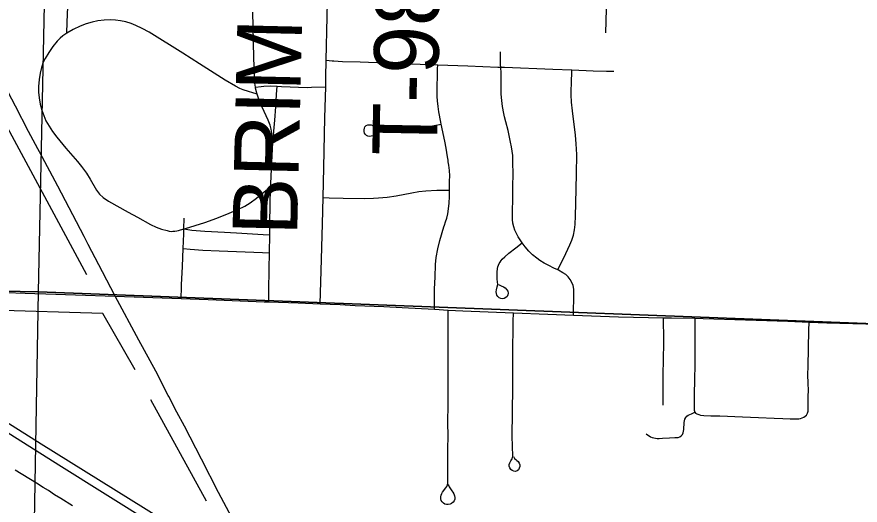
# Model space of a CAD drawing. Extents: x -59 to 43, y 0 to 22.
# Drawn here: x 24.177 to 24.918, y 18.165 to 18.594 of the extents above; entities that cross this region are included whole.
import ezdxf

# ---------------------------------------------------------------- set-up
doc = ezdxf.new("R2010")
doc.units = 0
for name, color, linetype in [('Default', 7, 'Continuous'), ('GM_X_City_Street', 7, 'Continuous'), ('GM_X_County_Road', 7, 'Continuous'), ('GM_X_Minor_River', 7, 'Continuous'), ('GM_X_Rail_Line', 7, 'Continuous'), ('GM_X_Section', 7, 'Continuous'), ('GM_X_State_Route', 7, 'Continuous'), ('GM_X_Township_Road', 7, 'Continuous'), ('GM_X_Township_Road_Text', 7, 'Continuous')]:
    doc.layers.add(name, color=color, linetype=linetype)

msp = doc.modelspace()

# ---------------------------------------------------------------- linework, layer by layer
at = {"layer": 'Default'}
for points in [[(23.51667, 19.36712), (23.51667, 18.36457), (24.19635, 18.35229), (24.21701, 19.34715)], [(23.51667, 18.36457), (23.51667, 17.35203), (23.63449, 17.34676), (24.1786, 17.34343), (24.19635, 18.35229)]]:
    msp.add_lwpolyline(points, close=True, dxfattribs=at)
at = {"layer": 'GM_X_City_Street'}
for points in [[(24.66612, 18.33172), (24.66623, 18.33912), (24.6663, 18.34325), (24.66629, 18.34753), (24.66646, 18.35082), (24.66645, 18.35444), (24.66588, 18.35775), (24.66475, 18.36048), (24.66327, 18.36301), (24.66144, 18.36531), (24.6593, 18.36733), (24.65691, 18.36904), (24.65293, 18.37112), (24.65228, 18.37143), (24.64874, 18.37311), (24.64457, 18.37521), (24.64045, 18.37742), (24.63644, 18.37987), (24.63387, 18.38169), (24.63021, 18.38469), (24.62683, 18.38802), (24.62374, 18.3916), (24.621, 18.39528), (24.61751, 18.40066), (24.61598, 18.40342), (24.61466, 18.40631), (24.61363, 18.40934), (24.61299, 18.41245), (24.61265, 18.41559), (24.61255, 18.42031), (24.61268, 18.42574), (24.61279, 18.43107), (24.61295, 18.43699), (24.61296, 18.44506), (24.61311, 18.45559), (24.61294, 18.46611), (24.61277, 18.47203), (24.61161, 18.47943), (24.61079, 18.48355), (24.60983, 18.48795), (24.60862, 18.49392), (24.60666, 18.50135), (24.60551, 18.50587), (24.6049, 18.50895), (24.6039, 18.51509), (24.60293, 18.52281), (24.60259, 18.52596), (24.60254, 18.53207), (24.60268, 18.54243), (24.6027, 18.54415), (24.60227, 18.54948), (24.60203, 18.55152), (24.602, 18.55344), (24.60203, 18.5601), (24.60203, 18.56296)], [(24.44906, 18.55561), (24.45417, 18.5551), (24.4557, 18.55494), (24.46342, 18.55453), (24.4789, 18.55412), (24.50827, 18.55302), (24.54686, 18.55163), (24.57338, 18.55053), (24.59975, 18.54959), (24.60227, 18.54948), (24.60568, 18.54937), (24.64785, 18.54778), (24.66459, 18.54713), (24.68353, 18.54637), (24.69525, 18.54606), (24.70154, 18.546)], [(24.54401, 18.33695), (24.54395, 18.34982), (24.5442, 18.35476), (24.54457, 18.36524), (24.54505, 18.37634), (24.54567, 18.38239), (24.5469, 18.38989), (24.54876, 18.39744), (24.5524, 18.40933), (24.55288, 18.41078), (24.55381, 18.41355), (24.55491, 18.41694), (24.55577, 18.42076), (24.55636, 18.42518), (24.557, 18.43014), (24.55724, 18.43582), (24.55729, 18.44149), (24.55737, 18.44942), (24.55743, 18.45408), (24.55716, 18.45874), (24.55652, 18.46335), (24.55618, 18.46635), (24.55603, 18.46782), (24.55559, 18.4708), (24.55426, 18.47837), (24.55306, 18.48444), (24.54996, 18.49952), (24.54961, 18.50119), (24.54784, 18.51033), (24.5472, 18.51491), (24.54676, 18.52001), (24.54651, 18.52371), (24.54645, 18.52725), (24.54646, 18.53024), (24.5465, 18.53178), (24.54657, 18.54267), (24.54675, 18.54814), (24.54686, 18.55163)], [(24.65228, 18.37143), (24.65483, 18.37662), (24.65756, 18.38218), (24.66299, 18.39336), (24.66472, 18.39766), (24.66609, 18.40208), (24.66703, 18.40663), (24.66757, 18.41125), (24.668, 18.41899), (24.66829, 18.42965), (24.66884, 18.45593), (24.66903, 18.4729), (24.66861, 18.48219), (24.66789, 18.48992), (24.66528, 18.51119), (24.66442, 18.51884), (24.66417, 18.52526), (24.66451, 18.53933), (24.66454, 18.54243), (24.66459, 18.54713)], [(24.49589, 18.49355), (24.49471, 18.49304), (24.4935, 18.49204), (24.49222, 18.4909), (24.49112, 18.48984), (24.49009, 18.48921), (24.48855, 18.48884), (24.48694, 18.48874), (24.48551, 18.48888), (24.48426, 18.48936), (24.48339, 18.49028), (24.48253, 18.49163), (24.4822, 18.49306), (24.4822, 18.49442), (24.48249, 18.49593), (24.483, 18.49714), (24.48392, 18.49813), (24.48538, 18.49886), (24.48693, 18.49895), (24.48843, 18.49879), (24.48983, 18.49828), (24.49141, 18.49714), (24.49303, 18.49549), (24.4948, 18.49424), (24.49621, 18.49373), (24.50079, 18.49341), (24.51016, 18.49339), (24.51481, 18.49358), (24.52099, 18.49416), (24.52867, 18.49536), (24.54391, 18.49834), (24.54996, 18.49952)], [(24.44624, 18.43494), (24.45155, 18.43483), (24.464, 18.43458), (24.48269, 18.43432), (24.49044, 18.43443), (24.49499, 18.4347), (24.50264, 18.4354), (24.51031, 18.4365), (24.52406, 18.4392), (24.53018, 18.44026), (24.53634, 18.44095), (24.54626, 18.44149), (24.55317, 18.44149), (24.55729, 18.44149)], [(24.60016, 18.35862), (24.60269, 18.35752), (24.60453, 18.35671), (24.60623, 18.35561), (24.60766, 18.35409), (24.60835, 18.35269), (24.60864, 18.35116), (24.60848, 18.34962), (24.60783, 18.34822), (24.60676, 18.3471), (24.60537, 18.34641), (24.60382, 18.34618), (24.60229, 18.34641), (24.60089, 18.34708), (24.59973, 18.34812), (24.59888, 18.34943), (24.59839, 18.3509), (24.59835, 18.35236), (24.59851, 18.35409), (24.59909, 18.35649), (24.59968, 18.35866), (24.5992, 18.36326), (24.59913, 18.36955), (24.59942, 18.37266), (24.59975, 18.37416), (24.60024, 18.37557), (24.60088, 18.37696), (24.60164, 18.37832), (24.60252, 18.37959), (24.60352, 18.3808), (24.60571, 18.38302), (24.60925, 18.38607), (24.61539, 18.39088), (24.621, 18.39528)], [(24.55621, 18.18341), (24.5564, 18.18248), (24.55695, 18.18108), (24.55815, 18.17913), (24.5592, 18.17754), (24.56006, 18.17637), (24.56111, 18.17482), (24.56171, 18.17315), (24.56197, 18.17162), (24.56183, 18.17008), (24.56127, 18.16866), (24.56034, 18.16744), (24.55913, 18.16647), (24.55772, 18.16581), (24.55621, 18.16547), (24.55466, 18.1655), (24.55317, 18.1659), (24.55185, 18.16668), (24.55077, 18.16778), (24.54999, 18.16912), (24.54955, 18.1706), (24.54949, 18.17214), (24.54978, 18.17365), (24.55037, 18.17508), (24.55117, 18.17641), (24.55405, 18.18007), (24.5549, 18.18137), (24.55551, 18.18277), (24.55582, 18.18428), (24.55576, 18.20442), (24.55589, 18.21059), (24.55583, 18.21525), (24.55597, 18.22454), (24.55589, 18.23848), (24.5561, 18.25241), (24.55593, 18.26325), (24.55613, 18.27409), (24.55605, 18.29113), (24.55616, 18.3283), (24.55615, 18.33622)], [(24.61332, 18.20749), (24.61433, 18.20588), (24.61539, 18.20486), (24.6165, 18.20406), (24.61751, 18.2031), (24.61839, 18.20176), (24.61888, 18.2003), (24.61892, 18.19876), (24.61854, 18.19727), (24.61777, 18.19597), (24.61662, 18.19503), (24.61519, 18.1946), (24.61367, 18.19473), (24.61226, 18.19535), (24.61108, 18.19635), (24.6102, 18.19763), (24.60971, 18.19909), (24.60963, 18.20063), (24.61009, 18.20219), (24.6111, 18.20386), (24.61221, 18.20562), (24.61281, 18.20784), (24.61276, 18.21041), (24.61255, 18.21409), (24.61256, 18.21717), (24.61237, 18.22489), (24.61237, 18.22799), (24.61247, 18.24355), (24.61288, 18.27156), (24.61298, 18.29646), (24.61327, 18.32603), (24.61335, 18.33372)], [(24.74491, 18.2526), (24.74488, 18.25636), (24.74492, 18.26259), (24.74503, 18.26728), (24.74503, 18.27665), (24.74526, 18.29541), (24.74538, 18.30466), (24.74537, 18.30937), (24.74538, 18.31249), (24.74538, 18.31719), (24.7453, 18.32188), (24.74515, 18.32952)], [(24.77277, 18.32898), (24.77278, 18.3166), (24.77264, 18.29927), (24.77256, 18.28701), (24.77247, 18.2763), (24.77222, 18.26079), (24.77198, 18.25305), (24.77202, 18.25021), (24.77215, 18.24841), (24.77267, 18.2465), (24.77326, 18.24574), (24.77459, 18.24496), (24.77608, 18.24441), (24.77758, 18.244), (24.78065, 18.24354), (24.78685, 18.24333), (24.79455, 18.24322), (24.81465, 18.24239), (24.8285, 18.24182), (24.84237, 18.24142), (24.85009, 18.24107), (24.85628, 18.24072), (24.86092, 18.24067), (24.864, 18.24082), (24.86553, 18.24105), (24.86701, 18.24146), (24.8684, 18.24212), (24.86961, 18.24307), (24.87071, 18.24396), (24.87171, 18.24556), (24.87221, 18.24754), (24.87233, 18.25038), (24.87218, 18.25483), (24.87232, 18.26062), (24.87245, 18.26568), (24.87232, 18.27196), (24.87207, 18.27925), (24.87219, 18.2869), (24.87292, 18.31836), (24.87309, 18.32566)], [(24.73004, 18.22751), (24.7312, 18.22651), (24.73246, 18.22565), (24.73381, 18.22494), (24.73523, 18.22436), (24.7367, 18.22392), (24.7382, 18.22362), (24.73972, 18.22347), (24.74125, 18.22345), (24.74432, 18.22363), (24.75046, 18.22391), (24.75507, 18.22417), (24.75813, 18.2244), (24.75956, 18.22495), (24.76079, 18.22582), (24.76176, 18.22697), (24.76245, 18.22833), (24.76286, 18.22979), (24.76307, 18.23132), (24.7633, 18.2375), (24.76354, 18.23902), (24.76397, 18.24048), (24.76468, 18.24181), (24.76568, 18.24294), (24.76694, 18.24381), (24.76833, 18.24448), (24.7697, 18.24512), (24.77267, 18.2465)], [(24.22605, 18.16437), (24.21591, 18.17074), (24.21045, 18.17411), (24.20514, 18.17763), (24.20034, 18.18051), (24.1945, 18.18423), (24.17593, 18.19577)]]:
    msp.add_lwpolyline(points, dxfattribs=at)
at = {"layer": 'GM_X_County_Road'}
for p, q in [((24.26357, 18.34829), (24.32145, 18.34626)), ((24.54401, 18.33695), (24.55615, 18.33622))]:
    msp.add_line(p, q, dxfattribs=at)
for points in [[(24.05155, 18.35317), (24.05354, 18.35315), (24.10325, 18.35249), (24.12329, 18.35228), (24.15918, 18.3519), (24.19308, 18.35084), (24.20267, 18.35054), (24.22887, 18.34957), (24.26357, 18.34829)], [(24.32145, 18.34626), (24.34518, 18.34542), (24.39446, 18.34351), (24.39853, 18.34336), (24.42427, 18.34244), (24.44365, 18.34165)], [(24.44365, 18.34165), (24.46127, 18.34096), (24.47442, 18.34035), (24.49944, 18.3392), (24.51574, 18.33845), (24.54401, 18.33695)], [(24.55615, 18.33622), (24.56906, 18.33547), (24.61335, 18.33372)], [(24.61335, 18.33372), (24.64352, 18.33253), (24.66612, 18.33172)], [(24.66612, 18.33172), (24.70553, 18.33029), (24.74515, 18.32952)], [(24.74515, 18.32952), (24.75211, 18.32939), (24.77277, 18.32898)], [(24.77277, 18.32898), (24.77999, 18.32878), (24.85449, 18.32633), (24.87309, 18.32566), (24.88863, 18.3251), (24.92277, 18.32407), (24.94397, 18.32326)]]:
    msp.add_lwpolyline(points, dxfattribs=at)
at = {"layer": 'GM_X_Minor_River'}
for points in [[(24.70035, 18.8265), (24.69746, 18.75395), (24.6965, 18.66351), (24.69414, 18.57955)], [(24.23865, 18.36726), (24.0972, 18.62991), (23.99498, 18.82037)], [(24.28106, 18.2836), (24.2528, 18.33316), (24.15497, 18.33614), (24.06698, 18.33704), (23.98922, 18.33812), (23.91035, 18.33998), (23.88019, 18.34013), (23.75221, 18.34297), (23.66576, 18.34536), (23.55881, 18.34701), (23.51667, 18.34767)], [(24.34375, 18.16839), (24.29499, 18.25749)]]:
    msp.add_lwpolyline(points, dxfattribs=at)
at = {"layer": 'GM_X_Rail_Line'}
for points in [[(24.85953, 17.57035), (24.84019, 17.76617), (24.82935, 17.81016), (24.79303, 17.84892), (24.19874, 18.21842), (23.51667, 18.64966)], [(23.51667, 18.64098), (24.21418, 18.20034), (24.75495, 17.86208), (24.75829, 17.57829), (24.85953, 17.57035)]]:
    msp.add_lwpolyline(points, dxfattribs=at)
at = {"layer": 'GM_X_Section'}
for points in [[(24.21701, 19.34715), (25.1966, 19.31798), (25.19616, 19.28425), (25.1906, 18.3142), (24.19635, 18.35229)], [(24.19635, 18.35229), (25.1906, 18.3142), (25.19112, 18.29638), (25.18772, 17.31279), (24.42943, 17.3409), (24.1786, 17.34343)]]:
    msp.add_lwpolyline(points, close=True, dxfattribs=at)
at = {"layer": 'GM_X_State_Route'}
msp.add_line((24.19713, 18.47511), (24.1957, 18.47781), dxfattribs=at)
for points in [[(24.1957, 18.47781), (24.18757, 18.4931), (24.17599, 18.51527), (24.16956, 18.52759), (24.14808, 18.56904), (24.13274, 18.59839)], [(24.26357, 18.34829), (24.2526, 18.36968), (24.24927, 18.37607), (24.24002, 18.39377), (24.23629, 18.40091), (24.21313, 18.445), (24.19713, 18.47511)], [(24.3102, 18.2612), (24.29921, 18.28243), (24.28436, 18.30977), (24.26357, 18.34829)], [(24.37768, 18.13223), (24.35431, 18.17608), (24.3395, 18.20518), (24.32441, 18.23417), (24.31783, 18.24653), (24.31066, 18.26031), (24.3102, 18.2612)]]:
    msp.add_lwpolyline(points, dxfattribs=at)
at = {"layer": 'GM_X_Township_Road'}
for p, q in [((24.32406, 18.40744), (24.32427, 18.41679)), ((24.39905, 18.38655), (24.39932, 18.40228))]:
    msp.add_line(p, q, dxfattribs=at)
for points in [[(24.44906, 18.55561), (24.44987, 18.59362), (24.4506, 18.63403), (24.4513, 18.67755), (24.4517, 18.69637)], [(24.22113, 18.57934), (24.22152, 18.58889), (24.22209, 18.60254), (24.22225, 18.60563)], [(24.38688, 18.53182), (24.38641, 18.53538), (24.38542, 18.5578), (24.38479, 18.58519), (24.38455, 18.59767)], [(24.38836, 18.52566), (24.38076, 18.52808), (24.37602, 18.52958), (24.37316, 18.53079), (24.36931, 18.5328), (24.3602, 18.53814), (24.33767, 18.5525), (24.32301, 18.56187), (24.29345, 18.58023), (24.28746, 18.58353), (24.28187, 18.58622), (24.27782, 18.58781), (24.27306, 18.58924), (24.2682, 18.59024), (24.26388, 18.59077), (24.25953, 18.59095), (24.25395, 18.59073), (24.24839, 18.59006), (24.24353, 18.58908), (24.23816, 18.58751), (24.23294, 18.58551), (24.22675, 18.58261), (24.22113, 18.57934)], [(24.22113, 18.57934), (24.21778, 18.57703), (24.21542, 18.57503), (24.21283, 18.57235), (24.20889, 18.56755), (24.20533, 18.56246), (24.20209, 18.55716), (24.2005, 18.55379), (24.19885, 18.5491), (24.19764, 18.54428), (24.19675, 18.53876), (24.1963, 18.53257), (24.19637, 18.5276), (24.19682, 18.52265), (24.19778, 18.51714), (24.19921, 18.51173), (24.20086, 18.50705), (24.20288, 18.50251), (24.20552, 18.49758), (24.20855, 18.49287), (24.2123, 18.48792), (24.22039, 18.4785), (24.23058, 18.46676), (24.23403, 18.46237), (24.23841, 18.45635), (24.24171, 18.45108), (24.24731, 18.44138), (24.24993, 18.43793), (24.25312, 18.43501), (24.25778, 18.43192), (24.27508, 18.42211), (24.28334, 18.41779), (24.29471, 18.41139), (24.29977, 18.40901), (24.30442, 18.40727), (24.30921, 18.40596), (24.31111, 18.40557), (24.31288, 18.40534), (24.31437, 18.40535), (24.31596, 18.40547), (24.31787, 18.40571), (24.31925, 18.40598), (24.32406, 18.40744)], [(24.44853, 18.53213), (24.44875, 18.54079), (24.44906, 18.55561)], [(24.38688, 18.53182), (24.39172, 18.53246), (24.3942, 18.53278), (24.39981, 18.53296), (24.40577, 18.53278)], [(24.38836, 18.52566), (24.38803, 18.52666), (24.387, 18.53097), (24.38688, 18.53182)], [(24.40214, 18.4834), (24.40381, 18.50287), (24.40482, 18.51475), (24.40538, 18.52542), (24.40577, 18.53278)], [(24.40577, 18.53278), (24.40981, 18.53265), (24.4323, 18.53177), (24.43604, 18.53185), (24.44853, 18.53213)], [(24.44624, 18.43494), (24.44701, 18.46153), (24.44785, 18.50505), (24.44853, 18.53213)], [(24.40214, 18.4834), (24.40176, 18.48459), (24.40155, 18.48585), (24.40146, 18.48713), (24.40131, 18.49146), (24.40074, 18.49502), (24.39975, 18.4985), (24.39796, 18.50306), (24.39263, 18.51429), (24.3898, 18.52128), (24.38836, 18.52566)], [(24.40032, 18.44475), (24.40047, 18.44747), (24.40093, 18.45987), (24.40214, 18.4834)], [(24.32406, 18.40744), (24.32547, 18.40788), (24.34223, 18.41318), (24.35283, 18.41687), (24.36387, 18.42116), (24.37129, 18.42441), (24.37739, 18.42754), (24.38216, 18.43049), (24.3877, 18.43452), (24.39448, 18.44001), (24.40032, 18.44475)], [(24.39932, 18.40228), (24.39942, 18.40772), (24.39968, 18.43325), (24.40032, 18.44475)], [(24.44365, 18.34165), (24.44453, 18.37071), (24.44568, 18.4118), (24.44624, 18.43494)], [(24.32339, 18.39029), (24.32396, 18.40309), (24.32406, 18.40744)], [(24.32406, 18.40744), (24.33092, 18.40649), (24.34223, 18.4056), (24.3596, 18.40474), (24.37015, 18.40413), (24.39374, 18.40264), (24.39932, 18.40228)], [(24.32145, 18.34626), (24.32188, 18.35643), (24.32196, 18.35829), (24.3227, 18.37447), (24.32339, 18.39029)], [(24.32339, 18.39029), (24.32951, 18.3898), (24.34069, 18.38888), (24.35501, 18.38814), (24.39304, 18.38677), (24.39905, 18.38655)], [(24.39853, 18.34336), (24.39862, 18.35297), (24.3988, 18.37227), (24.39905, 18.38655)]]:
    msp.add_lwpolyline(points, dxfattribs=at)

# ---------------------------------------------------------------- texts
at = {"layer": 'GM_X_Township_Road_Text'}
for s, rotation, p in [('T-98', 88.95303, (24.54616, 18.4713)), ('BRIM', 88.66739, (24.42342, 18.40134))]:
    msp.add_text(s, height=0.056818, rotation=rotation, dxfattribs=at).set_placement(p)

doc.saveas('drawing.dxf')
